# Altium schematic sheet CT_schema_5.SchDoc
size 252 x 258 mm
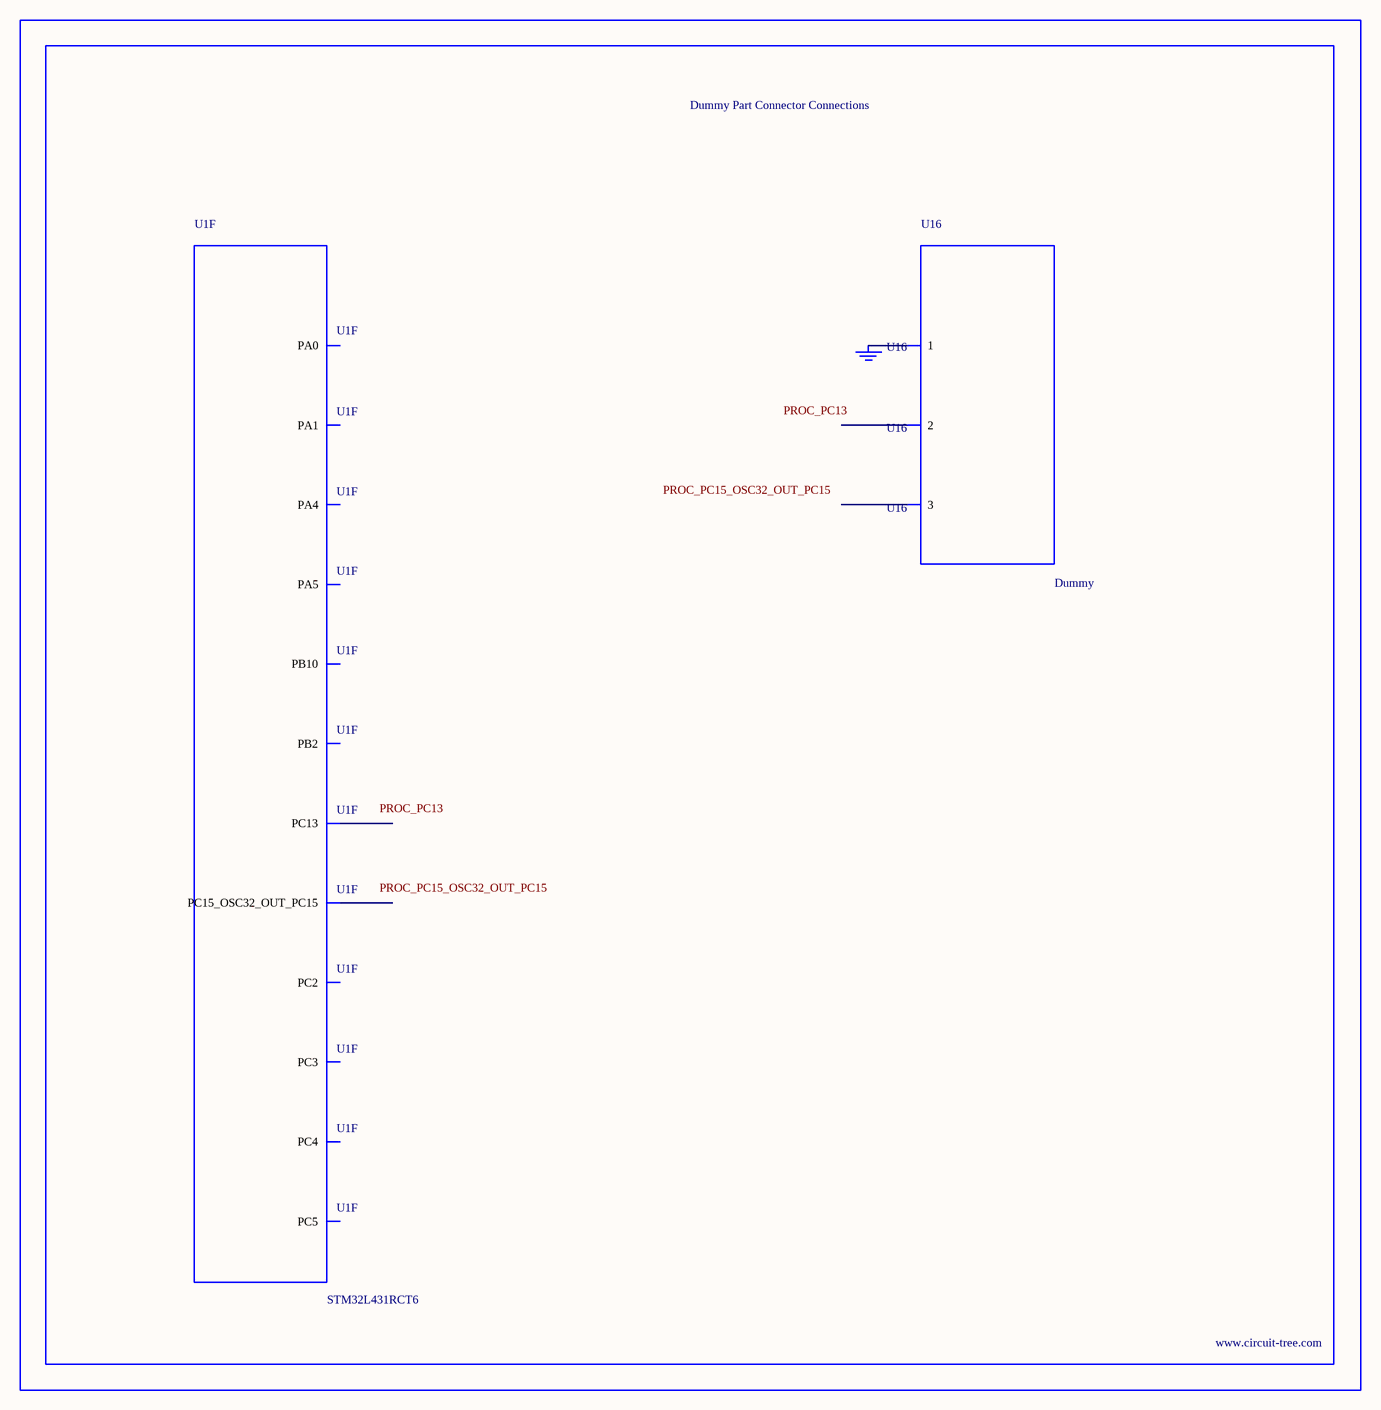
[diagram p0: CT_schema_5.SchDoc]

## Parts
BORDER4  (no value)
GND_INSTANCE_4_0  (no value)
U1  STM32L431RCT6  [LQFP64]  (part F of 6)
U16  Dummy  [DUMMY_PACKAGE_144]

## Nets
NetGND_INSTANCE_4_0_0: GND_INSTANCE_4_0.0(GND) U16.1

Not connected (* = marked no-connect by the designer): U1 2(PC13) 4(PC15_OSC32_OUT_PC15) 10(PC2) 11(PC3) 14(PA0) 15(PA1) 20(PA4) 21(PA5) 24(PC4) 25(PC5) 28(PB2) 29(PB10); U16 2 3

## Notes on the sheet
- Labels drawn without touching a wire or pin: PROC_PC13, PROC_PC15_OSC32_OUT_PC15

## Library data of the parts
BORDER4 = BORDER_PAGE4
GND_INSTANCE_4_0 = GND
